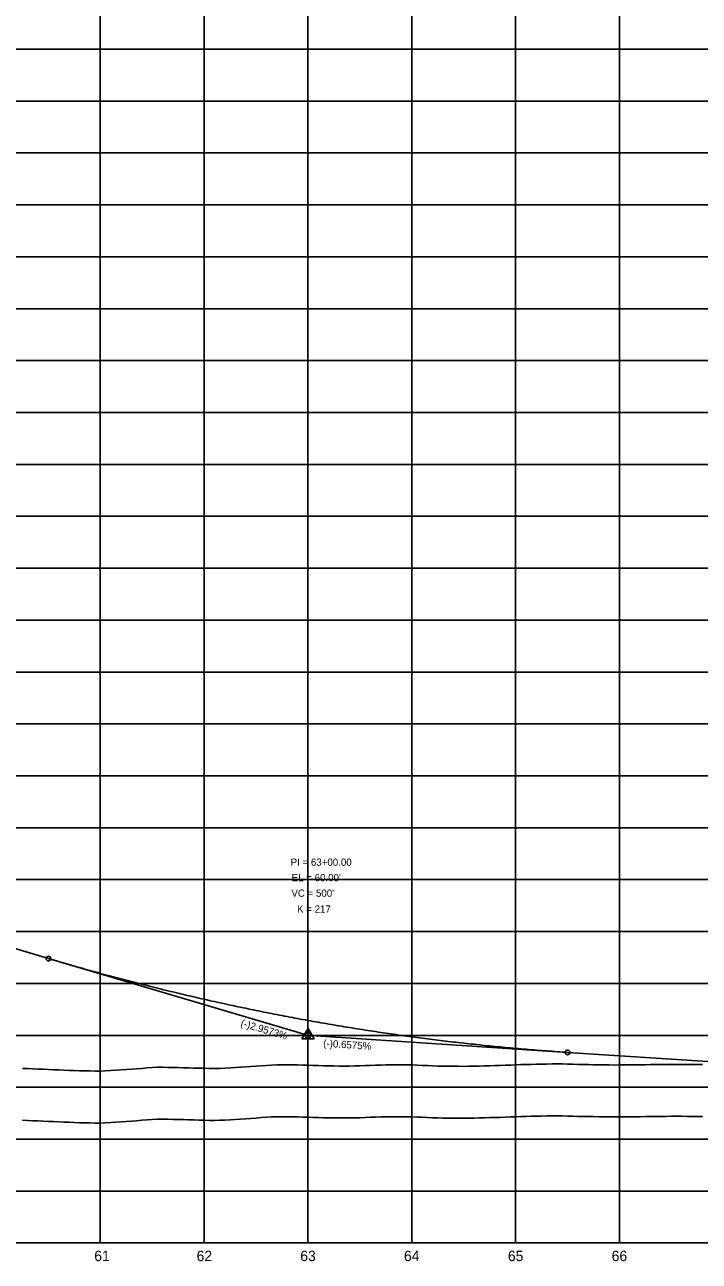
# Model space of a CAD drawing. Extents: x 2345490 to 2436403, y 465165 to 573888.
# Drawn here: x 2386349 to 2386998, y 564259 to 565450 of the extents above; entities that cross this region are included whole.
import ezdxf

# ---------------------------------------------------------------- set-up
doc = ezdxf.new("R2010")
doc.units = 0
for name, color, linetype in [('Old_Level_1', 7, 'Continuous'), ('Old_Level_2', 7, 'Continuous'), ('Old_Level_57', 7, 'Continuous'), ('Old_Level_62', 7, 'Continuous'), ('Old_Level_63', 7, 'Continuous')]:
    doc.layers.add(name, color=color, linetype=linetype)

msp = doc.modelspace()

# ---------------------------------------------------------------- linework, layer by layer
at = {"layer": 'Old_Level_1'}
for points in [[(2386346.5425, 564394.671), (2386351.5425, 564394.4615), (2386356.5425, 564394.246), (2386361.5425, 564394.0305), (2386366.5425, 564393.81475), (2386371.5425, 564393.60875)], [(2386371.5425, 564393.60875), (2386376.5425, 564393.405), (2386381.5425, 564393.20125), (2386386.5425, 564392.9975), (2386391.5425, 564392.79375), (2386396.5425, 564392.59), (2386401.5425, 564392.38625), (2386406.5425, 564392.28625), (2386411.5425, 564392.18725), (2386416.5425, 564392.0885), (2386421.5425, 564391.98975), (2386426.5425, 564392.231), (2386431.5425, 564392.55675), (2386436.5425, 564392.8825), (2386441.5425, 564393.208), (2386446.5425, 564393.565), (2386451.5425, 564393.94275), (2386456.5425, 564394.3205), (2386461.5425, 564394.6985), (2386466.5425, 564395.07625), (2386471.5425, 564395.45425), (2386476.5425, 564395.832), (2386481.5425, 564395.81875), (2386486.5425, 564395.70825), (2386491.5425, 564395.598), (2386496.5425, 564395.48775), (2386501.5425, 564395.35775), (2386506.5425, 564395.21275), (2386511.5425, 564395.06775), (2386516.5425, 564394.92275), (2386521.5425, 564394.7775), (2386526.5425, 564394.6325), (2386531.5425, 564394.4875), (2386536.5425, 564394.687), (2386541.5425, 564394.97175), (2386546.5425, 564395.2565), (2386551.5425, 564395.54125), (2386556.5425, 564395.86025), (2386561.5425, 564396.20875), (2386566.5425, 564396.55725), (2386571.5425, 564396.9055), (2386576.5425, 564397.254), (2386581.5425, 564397.6025), (2386586.5425, 564397.951), (2386591.5425, 564398.03), (2386596.5425, 564398.042), (2386601.5425, 564398.05375), (2386606.5425, 564398.06575), (2386611.5425, 564397.9905), (2386616.5425, 564397.834), (2386621.5425, 564397.6775), (2386626.5425, 564397.521), (2386631.5425, 564397.36425), (2386636.5425, 564397.2075), (2386641.5425, 564397.051), (2386646.5425, 564397.00575), (2386651.5425, 564396.98825), (2386656.5425, 564396.97075), (2386661.5425, 564396.95325), (2386666.5425, 564397.0375), (2386671.5425, 564397.21225), (2386676.5425, 564397.38725), (2386681.5425, 564397.56225), (2386686.5425, 564397.73725), (2386691.5425, 564397.9125), (2386696.5425, 564398.0875), (2386701.5425, 564398.1325), (2386706.5425, 564398.14525), (2386711.5425, 564398.15825), (2386716.5425, 564398.171), (2386721.5425, 564398.05075), (2386726.5425, 564397.8405), (2386731.5425, 564397.63025), (2386736.5425, 564397.41975), (2386741.5425, 564397.2095), (2386746.5425, 564396.99875), (2386751.5425, 564396.78825), (2386756.5425, 564396.7305), (2386761.5425, 564396.711), (2386766.5425, 564396.69125), (2386771.5425, 564396.6715), (2386776.5425, 564396.75775), (2386781.5425, 564396.88), (2386786.5425, 564397.00225), (2386791.5425, 564397.1245), (2386796.5425, 564397.247), (2386801.5425, 564397.36925), (2386806.5425, 564397.4915), (2386811.5425, 564397.6975), (2386816.5425, 564397.92475), (2386821.5425, 564398.152), (2386826.5425, 564398.3795), (2386831.5425, 564398.48725), (2386836.5425, 564398.5945), (2386841.5425, 564398.70175), (2386846.5425, 564398.809), (2386851.5425, 564398.916), (2386856.5425, 564399.02275), (2386861.5425, 564399.1295), (2386866.5425, 564399.00075), (2386871.5425, 564398.8105)], [(2386871.5425, 564398.8105), (2386876.5425, 564398.62), (2386881.5425, 564398.472), (2386886.5425, 564398.3965), (2386891.5425, 564398.32125), (2386896.5425, 564398.246), (2386901.5425, 564398.1705), (2386906.5425, 564398.09525), (2386911.5425, 564398.02), (2386916.5425, 564397.94475), (2386921.5425, 564397.96975), (2386926.5425, 564398.02275), (2386931.5425, 564398.07575), (2386936.5425, 564398.13375), (2386941.5425, 564398.19275), (2386946.5425, 564398.25175), (2386951.5425, 564398.31075), (2386956.5425, 564398.37), (2386961.5425, 564398.429), (2386966.5425, 564398.488), (2386971.5425, 564398.547), (2386976.5425, 564398.544), (2386981.5425, 564398.5215), (2386986.5425, 564398.486), (2386991.5425, 564398.43875), (2386996.5425, 564398.3915), (2387001.5425, 564398.344)]]:
    msp.add_lwpolyline(points, dxfattribs=at)
at = {"layer": 'Old_Level_2'}
for p, q in [((2386171.5425, 564609.614), (2386371.5425, 564550.46725)), ((2386371.5425, 564550.46725), (2386618.9055, 564477.31375)), ((2386871.5425, 564460.0965), (2386624.28675, 564476.3535)), ((2386871.5425, 564460.0965), (2387021.5425, 564450.234))]:
    msp.add_line(p, q, dxfattribs=at)
msp.add_lwpolyline([(2386615.748, 564473.06175), (2386627.4905, 564473.06175), (2386621.6195, 564483.1875)], close=True, dxfattribs=at)
for centre, radius in [((2386371.5425, 564550.46725), 2.25), ((2386621.5425, 564476.534), 2.75), ((2386871.5425, 564460.0965), 2.25)]:
    msp.add_circle(centre, radius, dxfattribs=at)
msp.add_spline([(2386371.5425, 564550.46725), (2386381.5425, 564547.53275), (2386391.5425, 564544.6445), (2386401.5425, 564541.80225), (2386411.5425, 564539.00575), (2386421.5425, 564536.2555), (2386431.5425, 564533.55125), (2386441.5425, 564530.89275), (2386451.5425, 564528.2805), (2386461.5425, 564525.714), (2386471.5425, 564523.19375), (2386481.5425, 564520.71925), (2386491.5425, 564518.291), (2386501.5425, 564515.9085), (2386511.5425, 564513.57225), (2386521.5425, 564511.28175), (2386531.5425, 564509.0375), (2386541.5425, 564506.839), (2386551.5425, 564504.68675), (2386561.5425, 564502.58025), (2386571.5425, 564500.52), (2386581.5425, 564498.5055), (2386591.5425, 564496.537), (2386601.5425, 564494.61475), (2386611.5425, 564492.73825), (2386621.5425, 564490.90775), (2386631.5425, 564489.1235), (2386641.5425, 564487.385), (2386651.5425, 564485.6925), (2386661.5425, 564484.04625), (2386671.5425, 564482.44575), (2386681.5425, 564480.89125), (2386691.5425, 564479.38275), (2386701.5425, 564477.9205), (2386711.5425, 564476.504), (2386721.5425, 564475.1335), (2386731.5425, 564473.809), (2386741.5425, 564472.5305), (2386751.5425, 564471.29825), (2386761.5425, 564470.11175), (2386771.5425, 564468.97125), (2386781.5425, 564467.87675), (2386791.5425, 564466.82825), (2386801.5425, 564465.82575), (2386811.5425, 564464.86925), (2386821.5425, 564463.95875), (2386831.5425, 564463.09425), (2386841.5425, 564462.27575), (2386851.5425, 564461.50325), (2386861.5425, 564460.77675), (2386871.5425, 564460.0965)], degree=3, dxfattribs=at)
at = {"layer": 'Old_Level_57'}
for p, q in [((2386421.5425, 564276.534), (2386421.5425, 566615.2835)), ((2386521.54225, 564276.534), (2386521.54225, 566615.2835)), ((2386621.542, 564276.534), (2386621.542, 566615.2835)), ((2386721.54225, 564276.534), (2386721.54225, 566615.2835)), ((2386821.54225, 564276.534), (2386821.54225, 566615.2835)), ((2386921.54225, 564276.534), (2386921.54225, 566615.2835)), ((2381271.5425, 565426.534), (2410861.12275, 565426.534)), ((2381271.5425, 565376.534), (2410861.12275, 565376.534)), ((2381271.5425, 565326.534), (2410861.12275, 565326.534)), ((2381271.5425, 565276.534), (2410861.12275, 565276.534)), ((2381271.5425, 565226.534), (2410861.12275, 565226.534)), ((2381271.5425, 565176.534), (2410861.12275, 565176.534)), ((2381271.5425, 565126.534), (2410861.12275, 565126.534)), ((2381271.5425, 565076.534), (2410861.12275, 565076.534)), ((2381271.5425, 565026.534), (2410861.12275, 565026.534)), ((2381271.5425, 564976.534), (2410861.12275, 564976.534)), ((2381271.5425, 564926.534), (2410861.12275, 564926.534)), ((2381271.5425, 564876.534), (2410861.12275, 564876.534)), ((2381271.5425, 564826.534), (2410861.12275, 564826.534)), ((2381271.54275, 564776.534), (2410861.123, 564776.534)), ((2381271.5425, 564726.534), (2410861.12275, 564726.534)), ((2381271.54275, 564676.534), (2410861.123, 564676.534)), ((2381271.5425, 564626.534), (2410861.12275, 564626.534)), ((2381271.54275, 564576.534), (2410861.123, 564576.534)), ((2381271.5425, 564526.534), (2410861.12275, 564526.534)), ((2381271.54275, 564476.534), (2410861.123, 564476.534)), ((2381271.5425, 564426.534), (2410861.12275, 564426.534)), ((2381271.54275, 564376.534), (2410861.123, 564376.534)), ((2381271.5425, 564326.534), (2410861.12275, 564326.534)), ((2381271.54275, 564276.534), (2410861.123, 564276.534))]:
    msp.add_line(p, q, dxfattribs=at)
at = {"layer": 'Old_Level_63'}
msp.add_line((2381321.5425, 564276.534), (2406689.937, 564276.534), dxfattribs=at)
for points in [[(2386346.5425, 564444.67075), (2386351.5425, 564444.46125), (2386356.5425, 564444.24575), (2386361.5425, 564444.03025), (2386366.5425, 564443.8145), (2386371.5425, 564443.6085)], [(2386371.5425, 564443.6085), (2386376.5425, 564443.40475), (2386381.5425, 564443.201), (2386386.5425, 564442.99725), (2386391.5425, 564442.7935), (2386396.5425, 564442.58975), (2386401.5425, 564442.386), (2386406.5425, 564442.286), (2386411.5425, 564442.187), (2386416.5425, 564442.08825), (2386421.5425, 564441.9895), (2386426.5425, 564442.23075), (2386431.5425, 564442.5565), (2386436.5425, 564442.88225), (2386441.5425, 564443.20775), (2386446.5425, 564443.56475), (2386451.5425, 564443.9425), (2386456.5425, 564444.32025), (2386461.5425, 564444.69825), (2386466.5425, 564445.076), (2386471.5425, 564445.454), (2386476.5425, 564445.83175), (2386481.5425, 564445.8185), (2386486.5425, 564445.708), (2386491.5425, 564445.59775), (2386496.5425, 564445.4875), (2386501.5425, 564445.3575), (2386506.5425, 564445.2125), (2386511.5425, 564445.0675), (2386516.5425, 564444.9225), (2386521.5425, 564444.77725), (2386526.5425, 564444.63225), (2386531.5425, 564444.48725), (2386536.5425, 564444.68675), (2386541.5425, 564444.9715), (2386546.5425, 564445.25625), (2386551.5425, 564445.541), (2386556.5425, 564445.86), (2386561.5425, 564446.2085), (2386566.5425, 564446.557), (2386571.5425, 564446.90525), (2386576.5425, 564447.25375), (2386581.5425, 564447.60225), (2386586.5425, 564447.95075), (2386591.5425, 564448.02975), (2386596.5425, 564448.04175), (2386601.5425, 564448.0535), (2386606.5425, 564448.0655), (2386611.5425, 564447.99025), (2386616.5425, 564447.83375), (2386621.5425, 564447.67725), (2386626.5425, 564447.52075), (2386631.5425, 564447.364), (2386636.5425, 564447.20725), (2386641.5425, 564447.05075), (2386646.5425, 564447.0055), (2386651.5425, 564446.988), (2386656.5425, 564446.9705), (2386661.5425, 564446.953), (2386666.5425, 564447.03725), (2386671.5425, 564447.212), (2386676.5425, 564447.387), (2386681.5425, 564447.562), (2386686.5425, 564447.737), (2386691.5425, 564447.91225), (2386696.5425, 564448.08725), (2386701.5425, 564448.13225), (2386706.5425, 564448.145), (2386711.5425, 564448.158), (2386716.5425, 564448.17075), (2386721.5425, 564448.0505), (2386726.5425, 564447.84025), (2386731.5425, 564447.63), (2386736.5425, 564447.4195), (2386741.5425, 564447.20925), (2386746.5425, 564446.9985), (2386751.5425, 564446.788), (2386756.5425, 564446.73025), (2386761.5425, 564446.71075), (2386766.5425, 564446.691), (2386771.5425, 564446.67125), (2386776.5425, 564446.7575), (2386781.5425, 564446.87975), (2386786.5425, 564447.002), (2386791.5425, 564447.12425), (2386796.5425, 564447.24675), (2386801.5425, 564447.369), (2386806.5425, 564447.49125), (2386811.5425, 564447.69725), (2386816.5425, 564447.9245), (2386821.5425, 564448.15175), (2386826.5425, 564448.37925), (2386831.5425, 564448.487), (2386836.5425, 564448.59425), (2386841.5425, 564448.7015), (2386846.5425, 564448.80875), (2386851.5425, 564448.91575), (2386856.5425, 564449.0225), (2386861.5425, 564449.12925), (2386866.5425, 564449.0005), (2386871.5425, 564448.81025)], [(2386871.5425, 564448.81025), (2386876.5425, 564448.61975), (2386881.5425, 564448.47175), (2386886.5425, 564448.39625), (2386891.5425, 564448.321), (2386896.5425, 564448.24575), (2386901.5425, 564448.17025), (2386906.5425, 564448.095), (2386911.5425, 564448.01975), (2386916.5425, 564447.9445), (2386921.5425, 564447.9695), (2386926.5425, 564448.0225), (2386931.5425, 564448.0755), (2386936.5425, 564448.1335), (2386941.5425, 564448.1925), (2386946.5425, 564448.2515), (2386951.5425, 564448.3105), (2386956.5425, 564448.36975), (2386961.5425, 564448.42875), (2386966.5425, 564448.48775), (2386971.5425, 564448.54675), (2386976.5425, 564448.54375), (2386981.5425, 564448.52125), (2386986.5425, 564448.48575), (2386991.5425, 564448.4385), (2386996.5425, 564448.39125), (2387001.5425, 564448.34375)]]:
    msp.add_lwpolyline(points, dxfattribs=at)

# ---------------------------------------------------------------- texts
at = {"layer": 'Old_Level_2'}
for s, height, p in [('PI = 63+00.00', 7.0000005, (2386604.845, 564639.87525)), ("EL = 60.00'", 7.0000005, (2386605.86175, 564624.96075)), ("VC = 500'", 7.000001, (2386605.58025, 564610.015)), ('K = 217', 7.000001, (2386611.02925, 564594.70775))]:
    msp.add_text(s, height=height, dxfattribs=at).set_placement(p)
for s, rotation, p in [('(-)2.9573%', 343.52529444, (2386556.19825, 564485.43)), ('(-)0.6575%', 356.23821667, (2386636.0545, 564465.558))]:
    msp.add_text(s, height=7.000001, rotation=rotation, dxfattribs=at).set_placement(p)
at = {"layer": 'Old_Level_62'}
for s, p in [('61', (2386415.7685, 564259.034)), ('62', (2386514.31675, 564259.034)), ('63', (2386614.1515, 564259.034)), ('64', (2386713.994, 564259.034)), ('65', (2386814.0865, 564259.034)), ('66', (2386914.0275, 564259.034))]:
    msp.add_text(s, height=10.000001, dxfattribs=at).set_placement(p)

doc.saveas('drawing.dxf')
